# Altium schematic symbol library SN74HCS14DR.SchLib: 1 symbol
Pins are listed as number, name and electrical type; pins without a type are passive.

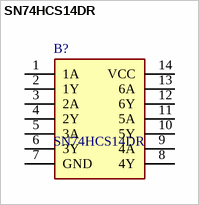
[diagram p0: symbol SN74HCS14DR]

## SN74HCS14DR
designator B?
Inverters Hex inverter with Schmitt-trigger inputs; Manufacturer_Name: Texas Instruments; Geometry.Height: 1.75mm
footprint SOIC127P600X175-14N
pins: 1 1A, 2 1Y, 3 2A, 4 2Y, 5 3A, 6 3Y, 7 GND, 8 4Y, 9 4A, 10 5Y, 11 5A, 12 6Y, 13 6A, 14 VCC (power)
